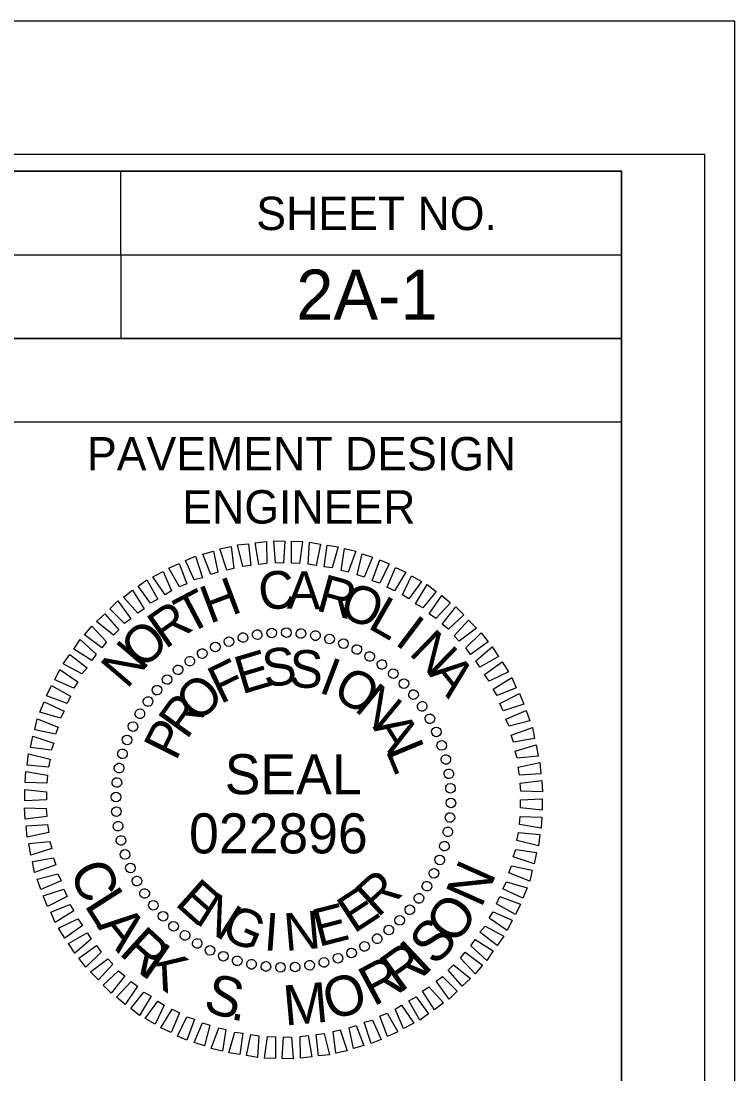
# Model space of a CAD drawing. Extents: x 1593595 to 1594166, y 741647 to 741854.
# Drawn here: x 1594128.53 to 1594141.36, y 741815.33 to 741834.26 of the extents above; entities that cross this region are included whole.
import ezdxf

# ---------------------------------------------------------------- set-up
doc = ezdxf.new("R2010")
doc.units = 0
for name, color, linetype in [('Sheet Cutting Line CELL', 7, 'Continuous'), ('Sheet Data Field CELL', 7, 'Continuous'), ('Sheet PE Seal Cell', 7, 'Continuous'), ('Sheet Plan CELL', 7, 'Continuous'), ('Sheet Plan Layout CELL', 7, 'Continuous'), ('Sheet Plot Border Inside CELL', 7, 'Continuous'), ('Sheet Plot Border Outside CELL', 7, 'Continuous')]:
    doc.layers.add(name, color=color, linetype=linetype)

msp = doc.modelspace()

# ---------------------------------------------------------------- linework, layer by layer
at = {"layer": 'Sheet Cutting Line CELL'}
msp.add_line((1594141.358, 741834.259), (1593939.338, 741834.259), dxfattribs=at)
at = {"layer": 'Sheet PE Seal Cell'}
for p, q in [((1594133.033, 741823.261), (1594133.033, 741823.261)), ((1594133.297, 741823.267), (1594133.297, 741823.267)), ((1594133.561, 741823.249), (1594133.561, 741823.249)), ((1594132.259, 741823.105), (1594132.259, 741823.105)), ((1594132.511, 741823.177), (1594132.511, 741823.177)), ((1594132.775, 741823.225), (1594132.775, 741823.225)), ((1594133.819, 741823.207), (1594133.819, 741823.207)), ((1594134.071, 741823.153), (1594134.071, 741823.153)), ((1594134.323, 741823.069), (1594134.323, 741823.069)), ((1594131.785, 741822.889), (1594131.785, 741822.889)), ((1594132.019, 741823.009), (1594132.019, 741823.009)), ((1594134.563, 741822.961), (1594134.563, 741822.961)), ((1594131.557, 741822.751), (1594131.557, 741822.751)), ((1594134.797, 741822.841), (1594134.797, 741822.841)), ((1594135.013, 741822.691), (1594135.013, 741822.691)), ((1594131.347, 741822.601), (1594131.347, 741822.601)), ((1594135.223, 741822.529), (1594135.223, 741822.529)), ((1594131.149, 741822.421), (1594131.149, 741822.421)), ((1594135.409, 741822.349), (1594135.409, 741822.349)), ((1594130.969, 741822.235), (1594130.969, 741822.235)), ((1594135.589, 741822.151), (1594135.589, 741822.151)), ((1594130.807, 741822.025), (1594130.807, 741822.025)), ((1594135.739, 741821.941), (1594135.739, 741821.941)), ((1594130.657, 741821.809), (1594130.657, 741821.809)), ((1594135.877, 741821.713), (1594135.877, 741821.713)), ((1594130.537, 741821.575), (1594130.537, 741821.575)), ((1594130.429, 741821.335), (1594130.429, 741821.335)), ((1594135.997, 741821.479), (1594135.997, 741821.479)), ((1594136.093, 741821.239), (1594136.093, 741821.239)), ((1594130.345, 741821.083), (1594130.345, 741821.083)), ((1594136.165, 741820.987), (1594136.165, 741820.987)), ((1594130.291, 741820.831), (1594130.291, 741820.831)), ((1594136.213, 741820.723), (1594136.213, 741820.723)), ((1594130.249, 741820.573), (1594130.249, 741820.573)), ((1594136.249, 741820.465), (1594136.249, 741820.465)), ((1594130.231, 741820.309), (1594130.231, 741820.309)), ((1594133.243, 741820.255), (1594133.243, 741820.255)), ((1594136.255, 741820.201), (1594136.255, 741820.201)), ((1594130.237, 741820.045), (1594130.237, 741820.045)), ((1594136.237, 741819.937), (1594136.237, 741819.937)), ((1594130.273, 741819.787), (1594130.273, 741819.787)), ((1594136.195, 741819.679), (1594136.195, 741819.679)), ((1594130.321, 741819.523), (1594130.321, 741819.523)), ((1594130.393, 741819.271), (1594130.393, 741819.271)), ((1594136.141, 741819.427), (1594136.141, 741819.427)), ((1594136.057, 741819.175), (1594136.057, 741819.175)), ((1594130.489, 741819.031), (1594130.489, 741819.031)), ((1594135.949, 741818.935), (1594135.949, 741818.935)), ((1594130.609, 741818.797), (1594130.609, 741818.797)), ((1594135.829, 741818.701), (1594135.829, 741818.701)), ((1594130.747, 741818.569), (1594130.747, 741818.569)), ((1594130.897, 741818.359), (1594130.897, 741818.359)), ((1594135.679, 741818.485), (1594135.679, 741818.485)), ((1594131.077, 741818.161), (1594131.077, 741818.161)), ((1594135.517, 741818.275), (1594135.517, 741818.275)), ((1594131.263, 741817.981), (1594131.263, 741817.981)), ((1594135.337, 741818.089), (1594135.337, 741818.089)), ((1594131.473, 741817.819), (1594131.473, 741817.819)), ((1594134.929, 741817.759), (1594134.929, 741817.759)), ((1594135.139, 741817.909), (1594135.139, 741817.909)), ((1594131.689, 741817.669), (1594131.689, 741817.669)), ((1594131.923, 741817.549), (1594131.923, 741817.549)), ((1594134.701, 741817.621), (1594134.701, 741817.621)), ((1594132.163, 741817.441), (1594132.163, 741817.441)), ((1594134.227, 741817.405), (1594134.227, 741817.405)), ((1594134.467, 741817.501), (1594134.467, 741817.501)), ((1594132.415, 741817.357), (1594132.415, 741817.357)), ((1594132.667, 741817.303), (1594132.667, 741817.303)), ((1594132.925, 741817.261), (1594132.925, 741817.261)), ((1594133.189, 741817.243), (1594133.189, 741817.243)), ((1594133.453, 741817.249), (1594133.453, 741817.249)), ((1594133.711, 741817.285), (1594133.711, 741817.285)), ((1594133.975, 741817.333), (1594133.975, 741817.333))]:
    msp.add_line(p, q, dxfattribs=at)
for points in [[(1594132.223, 741824.389), (1594132.097, 741824.767), (1594132.301, 741824.809), (1594132.349, 741824.419)], [(1594132.511, 741824.455), (1594132.415, 741824.839), (1594132.613, 741824.857), (1594132.655, 741824.473)], [(1594132.799, 741824.491), (1594132.733, 741824.875), (1594132.937, 741824.899), (1594132.943, 741824.509)], [(1594133.099, 741824.521), (1594133.069, 741824.911), (1594133.267, 741824.905), (1594133.243, 741824.515)], [(1594133.387, 741824.515), (1594133.387, 741824.905), (1594133.585, 741824.899), (1594133.531, 741824.509)], [(1594133.687, 741824.497), (1594133.711, 741824.887), (1594133.909, 741824.851), (1594133.831, 741824.473)], [(1594133.975, 741824.449), (1594134.029, 741824.833), (1594134.227, 741824.803), (1594134.119, 741824.431)], [(1594134.281, 741824.383), (1594134.341, 741824.773), (1594134.545, 741824.725), (1594134.407, 741824.353)], [(1594131.641, 741824.215), (1594131.485, 741824.563), (1594131.665, 741824.635), (1594131.791, 741824.251)], [(1594131.935, 741824.311), (1594131.797, 741824.671), (1594131.983, 741824.725), (1594132.061, 741824.353)], [(1594134.569, 741824.305), (1594134.659, 741824.677), (1594134.845, 741824.617), (1594134.695, 741824.263)], [(1594134.839, 741824.197), (1594134.977, 741824.575), (1594135.145, 741824.503), (1594134.977, 741824.155)], [(1594131.119, 741823.945), (1594130.897, 741824.269), (1594131.083, 741824.365), (1594131.233, 741824.017)], [(1594131.377, 741824.089), (1594131.185, 741824.425), (1594131.371, 741824.509), (1594131.509, 741824.143)], [(1594135.109, 741824.083), (1594135.259, 741824.437), (1594135.445, 741824.353), (1594135.241, 741824.017)], [(1594130.855, 741823.795), (1594130.633, 741824.101), (1594130.789, 741824.215), (1594130.987, 741823.867)], [(1594135.385, 741823.945), (1594135.547, 741824.287), (1594135.727, 741824.185), (1594135.499, 741823.873)], [(1594130.627, 741823.615), (1594130.369, 741823.903), (1594130.531, 741824.029), (1594130.741, 741823.693)], [(1594135.619, 741823.783), (1594135.829, 741824.131), (1594135.985, 741824.005), (1594135.751, 741823.711)], [(1594130.387, 741823.429), (1594130.123, 741823.693), (1594130.267, 741823.837), (1594130.501, 741823.513)], [(1594135.865, 741823.603), (1594136.087, 741823.933), (1594136.243, 741823.801), (1594135.979, 741823.519)], [(1594136.093, 741823.417), (1594136.339, 741823.729), (1594136.483, 741823.585), (1594136.207, 741823.327)], [(1594130.189, 741823.219), (1594129.883, 741823.465), (1594130.033, 741823.603), (1594130.285, 741823.315)], [(1594136.309, 741823.207), (1594136.567, 741823.489), (1594136.711, 741823.345), (1594136.399, 741823.111)], [(1594129.979, 741822.991), (1594129.667, 741823.225), (1594129.799, 741823.381), (1594130.063, 741823.099)], [(1594136.519, 741822.991), (1594136.795, 741823.261), (1594136.921, 741823.099), (1594136.603, 741822.871)], [(1594129.799, 741822.763), (1594129.475, 741822.967), (1594129.589, 741823.141), (1594129.877, 741822.877)], [(1594129.619, 741822.523), (1594129.283, 741822.703), (1594129.403, 741822.871), (1594129.715, 741822.631)], [(1594136.699, 741822.757), (1594136.993, 741823.009), (1594137.107, 741822.835), (1594136.771, 741822.643)], [(1594136.855, 741822.511), (1594137.173, 741822.739), (1594137.287, 741822.559), (1594136.939, 741822.391)], [(1594129.475, 741822.265), (1594129.133, 741822.415), (1594129.223, 741822.601), (1594129.547, 741822.379)], [(1594129.355, 741821.989), (1594128.983, 741822.127), (1594129.073, 741822.313), (1594129.415, 741822.121)], [(1594137.011, 741822.247), (1594137.347, 741822.457), (1594137.425, 741822.271), (1594137.083, 741822.133)], [(1594137.131, 741821.989), (1594137.485, 741822.169), (1594137.563, 741821.977), (1594137.191, 741821.857)], [(1594129.235, 741821.725), (1594128.863, 741821.833), (1594128.941, 741822.019), (1594129.301, 741821.851)], [(1594129.145, 741821.437), (1594128.773, 741821.515), (1594128.815, 741821.713), (1594129.193, 741821.563)], [(1594137.239, 741821.707), (1594137.605, 741821.863), (1594137.671, 741821.677), (1594137.299, 741821.581)], [(1594137.335, 741821.419), (1594137.719, 741821.557), (1594137.755, 741821.359), (1594137.377, 741821.293)], [(1594129.067, 741821.149), (1594128.695, 741821.197), (1594128.737, 741821.401), (1594129.115, 741821.275)], [(1594137.407, 741821.131), (1594137.785, 741821.245), (1594137.821, 741821.041), (1594137.443, 741821.005)], [(1594129.019, 741820.843), (1594128.635, 741820.879), (1594128.659, 741821.083), (1594129.049, 741820.987)], [(1594128.989, 741820.555), (1594128.599, 741820.567), (1594128.611, 741820.765), (1594129.001, 741820.699)], [(1594137.461, 741820.843), (1594137.851, 741820.927), (1594137.869, 741820.723), (1594137.485, 741820.699)], [(1594137.497, 741820.555), (1594137.887, 741820.603), (1594137.899, 741820.399), (1594137.509, 741820.411)], [(1594128.983, 741820.255), (1594128.593, 741820.237), (1594128.593, 741820.441), (1594128.983, 741820.399)], [(1594137.503, 741820.255), (1594137.893, 741820.273), (1594137.893, 741820.069), (1594137.503, 741820.111)], [(1594128.989, 741819.955), (1594128.599, 741819.907), (1594128.587, 741820.111), (1594128.977, 741820.099)], [(1594137.497, 741819.955), (1594137.887, 741819.943), (1594137.875, 741819.745), (1594137.485, 741819.811)], [(1594129.025, 741819.667), (1594128.635, 741819.583), (1594128.617, 741819.787), (1594129.001, 741819.811)], [(1594137.467, 741819.667), (1594137.851, 741819.631), (1594137.827, 741819.427), (1594137.437, 741819.523)], [(1594129.079, 741819.379), (1594128.701, 741819.265), (1594128.665, 741819.469), (1594129.043, 741819.505)], [(1594137.419, 741819.361), (1594137.791, 741819.313), (1594137.749, 741819.109), (1594137.371, 741819.235)], [(1594129.151, 741819.091), (1594128.767, 741818.953), (1594128.731, 741819.151), (1594129.109, 741819.217)], [(1594137.341, 741819.073), (1594137.713, 741818.995), (1594137.671, 741818.797), (1594137.293, 741818.947)], [(1594129.247, 741818.803), (1594128.881, 741818.647), (1594128.815, 741818.833), (1594129.187, 741818.929)], [(1594137.251, 741818.785), (1594137.623, 741818.677), (1594137.545, 741818.491), (1594137.185, 741818.659)], [(1594129.355, 741818.521), (1594129.001, 741818.341), (1594128.923, 741818.533), (1594129.295, 741818.653)], [(1594137.131, 741818.521), (1594137.503, 741818.383), (1594137.413, 741818.197), (1594137.071, 741818.389)], [(1594129.475, 741818.263), (1594129.139, 741818.053), (1594129.061, 741818.239), (1594129.403, 741818.377)], [(1594129.631, 741817.999), (1594129.313, 741817.771), (1594129.199, 741817.951), (1594129.547, 741818.119)], [(1594137.011, 741818.245), (1594137.353, 741818.095), (1594137.263, 741817.909), (1594136.939, 741818.131)], [(1594136.867, 741817.987), (1594137.203, 741817.807), (1594137.083, 741817.639), (1594136.771, 741817.879)], [(1594129.787, 741817.753), (1594129.493, 741817.501), (1594129.379, 741817.675), (1594129.715, 741817.867)], [(1594136.687, 741817.747), (1594137.011, 741817.543), (1594136.897, 741817.369), (1594136.609, 741817.633)], [(1594129.967, 741817.519), (1594129.691, 741817.249), (1594129.565, 741817.411), (1594129.883, 741817.639)], [(1594130.177, 741817.303), (1594129.919, 741817.021), (1594129.775, 741817.165), (1594130.087, 741817.399)], [(1594136.507, 741817.519), (1594136.819, 741817.285), (1594136.687, 741817.129), (1594136.423, 741817.411)], [(1594130.393, 741817.093), (1594130.147, 741816.781), (1594130.003, 741816.925), (1594130.279, 741817.183)], [(1594136.297, 741817.291), (1594136.603, 741817.045), (1594136.453, 741816.907), (1594136.201, 741817.195)], [(1594130.621, 741816.907), (1594130.399, 741816.577), (1594130.243, 741816.709), (1594130.507, 741816.991)], [(1594136.099, 741817.081), (1594136.363, 741816.817), (1594136.219, 741816.673), (1594135.985, 741816.997)], [(1594130.867, 741816.727), (1594130.657, 741816.379), (1594130.501, 741816.505), (1594130.735, 741816.799)], [(1594135.859, 741816.895), (1594136.117, 741816.607), (1594135.955, 741816.481), (1594135.745, 741816.817)], [(1594131.101, 741816.565), (1594130.939, 741816.223), (1594130.759, 741816.325), (1594130.987, 741816.637)], [(1594135.631, 741816.715), (1594135.853, 741816.409), (1594135.697, 741816.295), (1594135.499, 741816.643)], [(1594131.377, 741816.427), (1594131.227, 741816.073), (1594131.041, 741816.157), (1594131.245, 741816.493)], [(1594135.109, 741816.421), (1594135.301, 741816.085), (1594135.115, 741816.001), (1594134.977, 741816.367)], [(1594135.367, 741816.565), (1594135.589, 741816.241), (1594135.403, 741816.145), (1594135.253, 741816.493)], [(1594131.647, 741816.313), (1594131.509, 741815.935), (1594131.341, 741816.007), (1594131.509, 741816.355)], [(1594131.917, 741816.205), (1594131.827, 741815.833), (1594131.641, 741815.893), (1594131.791, 741816.247)], [(1594134.845, 741816.295), (1594135.001, 741815.947), (1594134.821, 741815.875), (1594134.695, 741816.259)], [(1594132.205, 741816.127), (1594132.145, 741815.737), (1594131.941, 741815.785), (1594132.079, 741816.157)], [(1594132.511, 741816.061), (1594132.457, 741815.677), (1594132.259, 741815.707), (1594132.367, 741816.079)], [(1594132.799, 741816.013), (1594132.775, 741815.623), (1594132.577, 741815.659), (1594132.655, 741816.037)], [(1594133.975, 741816.055), (1594134.071, 741815.671), (1594133.873, 741815.653), (1594133.831, 741816.037)], [(1594134.263, 741816.121), (1594134.389, 741815.743), (1594134.185, 741815.701), (1594134.137, 741816.091)], [(1594134.551, 741816.199), (1594134.689, 741815.839), (1594134.503, 741815.785), (1594134.425, 741816.157)], [(1594133.099, 741815.995), (1594133.099, 741815.605), (1594132.901, 741815.611), (1594132.955, 741816.001)], [(1594133.387, 741815.989), (1594133.417, 741815.599), (1594133.219, 741815.605), (1594133.243, 741815.995)], [(1594133.687, 741816.019), (1594133.753, 741815.635), (1594133.549, 741815.611), (1594133.543, 741816.001)]]:
    msp.add_lwpolyline(points, close=True, dxfattribs=at)
for centre, major_axis in [((1594132.515, 741823.175), (-0.0209, 0.0838)), ((1594132.772, 741823.227), (-0.0135, 0.0853)), ((1594133.033, 741823.257), (-0.006, 0.0862)), ((1594133.295, 741823.264), (0.0015, 0.0864)), ((1594133.557, 741823.248), (0.009, 0.0859)), ((1594133.817, 741823.209), (0.0165, 0.0848)), ((1594134.072, 741823.148), (0.0238, 0.0831)), ((1594132.019, 741823.004), (-0.0351, 0.0789)), ((1594132.263, 741823.1), (-0.0281, 0.0817)), ((1594134.321, 741823.064), (0.031, 0.0807)), ((1594134.562, 741822.96), (0.0379, 0.0777)), ((1594131.56, 741822.75), (-0.0483, 0.0716)), ((1594131.784, 741822.887), (-0.0419, 0.0756)), ((1594134.793, 741822.834), (0.0445, 0.0741)), ((1594131.349, 741822.594), (-0.0544, 0.0671)), ((1594135.012, 741822.69), (0.0508, 0.0699)), ((1594131.152, 741822.42), (-0.06, 0.0622)), ((1594135.217, 741822.526), (0.0567, 0.0652)), ((1594130.971, 741822.229), (-0.0652, 0.0567)), ((1594135.408, 741822.345), (0.0622, 0.06)), ((1594130.808, 741822.024), (-0.0699, 0.0508)), ((1594135.582, 741822.149), (0.0671, 0.0544)), ((1594130.663, 741821.805), (-0.0741, 0.0445)), ((1594135.738, 741821.938), (0.0716, 0.0483)), ((1594135.875, 741821.714), (0.0756, 0.0419)), ((1594130.538, 741821.574), (-0.0777, 0.0379)), ((1594135.992, 741821.479), (0.0789, 0.0351)), ((1594130.433, 741821.333), (-0.0807, 0.031)), ((1594130.35, 741821.084), (-0.0831, 0.0238)), ((1594136.088, 741821.235), (0.0817, 0.0281)), ((1594136.163, 741820.983), (0.0838, 0.0209)), ((1594130.288, 741820.829), (-0.0848, 0.0165)), ((1594136.215, 741820.726), (0.0853, 0.0135)), ((1594130.25, 741820.569), (-0.0859, 0.009)), ((1594130.234, 741820.307), (-0.0864, 0.0015)), ((1594136.245, 741820.465), (0.0862, 0.006)), ((1594136.252, 741820.202), (0.0864, -0.0015)), ((1594130.24, 741820.045), (-0.0862, -0.006)), ((1594136.236, 741819.94), (0.0859, -0.009)), ((1594130.27, 741819.784), (-0.0853, -0.0135)), ((1594136.197, 741819.68), (0.0848, -0.0165)), ((1594130.323, 741819.527), (-0.0838, -0.0209)), ((1594136.136, 741819.425), (0.0831, -0.0238)), ((1594130.397, 741819.275), (-0.0817, -0.0281)), ((1594136.052, 741819.176), (0.0807, -0.031)), ((1594130.493, 741819.031), (-0.0789, -0.0351)), ((1594130.61, 741818.796), (-0.0756, -0.0419)), ((1594135.948, 741818.935), (0.0777, -0.0379)), ((1594135.822, 741818.705), (0.0741, -0.0445)), ((1594130.748, 741818.572), (-0.0716, -0.0483)), ((1594135.678, 741818.486), (0.0699, -0.0508)), ((1594130.904, 741818.361), (-0.0671, -0.0544)), ((1594135.514, 741818.28), (0.0652, -0.0567)), ((1594131.078, 741818.164), (-0.0622, -0.06)), ((1594135.333, 741818.09), (0.06, -0.0622)), ((1594131.268, 741817.983), (-0.0567, -0.0652)), ((1594135.137, 741817.916), (0.0544, -0.0671)), ((1594131.474, 741817.82), (-0.0508, -0.0699)), ((1594131.693, 741817.675), (-0.0445, -0.0741)), ((1594134.926, 741817.76), (0.0483, -0.0716)), ((1594131.923, 741817.55), (-0.0379, -0.0777)), ((1594134.467, 741817.505), (0.0351, -0.0789)), ((1594134.702, 741817.622), (0.0419, -0.0756)), ((1594132.164, 741817.445), (-0.031, -0.0807)), ((1594132.413, 741817.362), (-0.0238, -0.0831)), ((1594132.668, 741817.3), (-0.0165, -0.0848)), ((1594133.714, 741817.282), (0.0135, -0.0853)), ((1594133.971, 741817.335), (0.0209, -0.0838)), ((1594134.223, 741817.409), (0.0281, -0.0817)), ((1594132.928, 741817.262), (-0.009, -0.0859)), ((1594133.19, 741817.246), (-0.0015, -0.0864)), ((1594133.453, 741817.252), (0.006, -0.0862))]:
    msp.add_ellipse(centre, major_axis=major_axis, ratio=0.999708, dxfattribs=at)
at = {"layer": 'Sheet Plan CELL'}
for p, q in [((1594130.313, 741831.553), (1594130.319, 741828.553)), ((1594115.31, 741830.056), (1594139.316, 741830.054)), ((1594115.312, 741828.551), (1594139.316, 741828.554)), ((1594115.312, 741828.551), (1594139.316, 741828.554))]:
    msp.add_line(p, q, dxfattribs=at)
for points in [[(1594139.321, 741831.56), (1593959.316, 741831.56), (1593959.316, 741705.56), (1594139.318, 741705.56)], [(1594115.312, 741831.562), (1594139.321, 741831.56), (1594139.316, 741828.554), (1594115.312, 741828.551)], [(1594127.318, 741827.053), (1594139.316, 741827.054), (1594139.318, 741813.553), (1594127.318, 741813.551)]]:
    msp.add_lwpolyline(points, close=True, dxfattribs=at)
at = {"layer": 'Sheet Plan Layout CELL'}
msp.add_lwpolyline([(1594110.606, 741806.182), (1594139.319, 741806.182), (1594139.322, 741831.56), (1594110.606, 741831.56)], close=True, dxfattribs=at)
at = {"layer": 'Sheet Plot Border Inside CELL'}
msp.add_lwpolyline([(1593940.898, 741705.259), (1594140.816, 741705.26), (1594140.818, 741831.859), (1593940.898, 741831.859)], close=True, dxfattribs=at)
at = {"layer": 'Sheet Plot Border Outside CELL'}
msp.add_lwpolyline([(1593939.338, 741702.859), (1594141.358, 741702.859), (1594141.358, 741834.259), (1593939.338, 741834.259)], close=True, dxfattribs=at)

# ---------------------------------------------------------------- texts
at = {"layer": 'Sheet Data Field CELL'}
msp.add_text('2A-1', height=0.9, rotation=0, dxfattribs=at).set_placement((1594133.473, 741828.89))
at = {"layer": 'Sheet PE Seal Cell'}
for s, height, rotation, p in [('C', 0.677, 6.2199, (1594132.829, 741823.657)), ('A', 0.677, 359.0203, (1594133.303, 741823.693)), ('H', 0.677, 20.6195, (1594131.917, 741823.417)), ('R', 0.677, 344.6211, (1594133.807, 741823.669)), ('T', 0.677, 27.8198, (1594131.527, 741823.219)), ('O', 0.677, 337.4212, (1594134.209, 741823.579)), ('L', 0.677, 330.2209, (1594134.737, 741823.357)), ('R', 0.677, 35.0205, (1594131.119, 741822.955)), ('O', 0.677, 42.2217, (1594130.705, 741822.583)), ('I', 0.677, 323.0201, (1594135.223, 741823.069)), ('N', 0.677, 315.8189, (1594135.481, 741822.883)), ('N', 0.677, 49.4235, (1594130.429, 741822.235)), ('E', 0.677, 16.6111, (1594132.493, 741822.151)), ('S', 0.677, 7.2556, (1594132.907, 741822.277)), ('S', 0.677, 357.9004, (1594133.339, 741822.283)), ('F', 0.677, 25.967, (1594132.109, 741821.971)), ('I', 0.677, 339.1896, (1594133.855, 741822.199)), ('A', 0.677, 308.6172, (1594135.835, 741822.529)), ('O', 0.677, 329.8335, (1594134.095, 741822.115)), ('O', 0.677, 44.6812, (1594131.713, 741821.617)), ('N', 0.677, 320.4766, (1594134.497, 741821.875)), ('R', 0.677, 54.0397, (1594131.503, 741821.323)), ('P', 0.677, 63.3989, (1594131.311, 741820.939)), ('A', 0.677, 301.7603, (1594134.839, 741821.563)), ('L', 0.677, 292.4008, (1594135.073, 741821.149)), ('SEAL', 0.7198, 360, (1594132.187, 741820.357)), ('C', 0.72, 292.9481, (1594129.387, 741818.989)), ('N', 0.72, 65.9082, (1594136.796, 741818.295)), ('R', 0.677, 42.4814, (1594134.935, 741818.125)), ('L', 0.72, 302.5303, (1594129.651, 741818.365)), ('E', 0.677, 318.2769, (1594131.275, 741818.377)), ('E', 0.677, 33.1241, (1594134.509, 741817.843)), ('N', 0.677, 327.634, (1594131.635, 741818.053)), ('O', 0.72, 54.3478, (1594136.332, 741817.623)), ('G', 0.677, 336.9902, (1594132.091, 741817.783)), ('E', 0.677, 14.4118, (1594133.873, 741817.609)), ('A', 0.72, 308.805, (1594129.879, 741817.984)), ('I', 0.677, 355.7012, (1594132.877, 741817.555)), ('N', 0.677, 5.0564, (1594133.279, 741817.537)), ('R', 0.72, 317.6453, (1594130.268, 741817.494)), ('S', 0.72, 47.0221, (1594135.971, 741817.25)), ('K', 0.72, 325.1256, (1594130.653, 741817.13)), ('R', 0.72, 35.7399, (1594135.33, 741816.775)), ('I', 0.72, 43.2201, (1594135.766, 741817.076)), ('R', 0.72, 28.2596, (1594134.86, 741816.533)), ('S', 0.72, 343.6099, (1594131.777, 741816.47)), ('M', 0.72, 5.1697, (1594133.27, 741816.197)), ('O', 0.72, 16.6992, (1594134.081, 741816.284)), ('.', 0.72, 350.9356, (1594132.272, 741816.314))]:
    msp.add_text(s, height=height, rotation=rotation, dxfattribs=at).set_placement(p)
msp.add_text('022896', height=0.7198, dxfattribs=at).set_placement((1594131.546, 741819.294))
at = {"layer": 'Sheet Plan CELL'}
for s, height, p in [('SHEET NO.', 0.6, (1594132.755, 741830.501)), ('PAVEMENT DESIGN', 0.60001, (1594129.712, 741826.18)), ('ENGINEER', 0.6, (1594131.425, 741825.224))]:
    msp.add_text(s, height=height, rotation=0, dxfattribs=at).set_placement(p)

doc.saveas('drawing.dxf')
